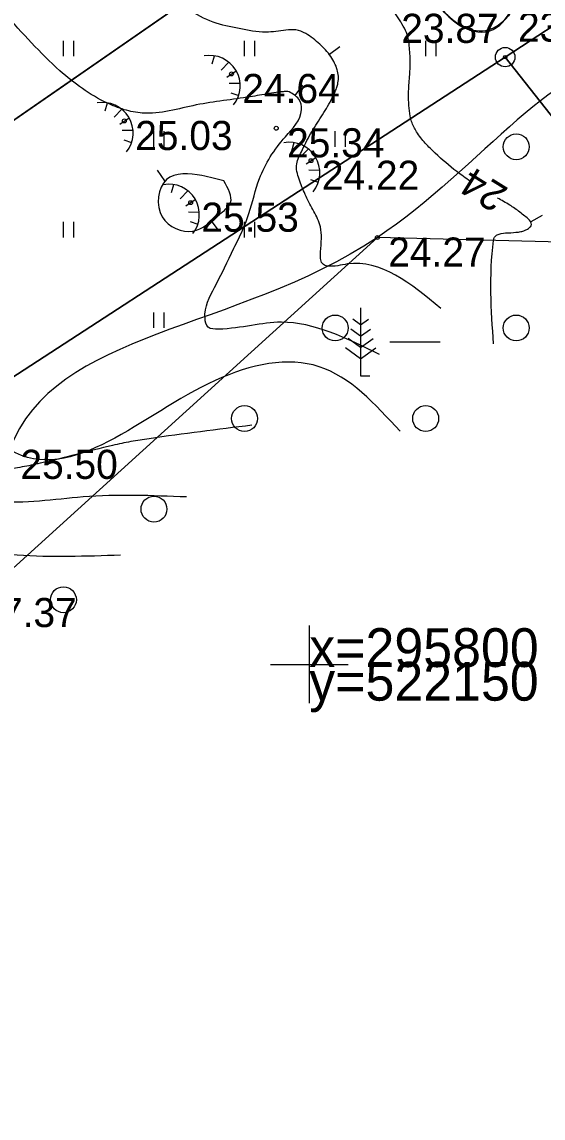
# Model space of a CAD drawing. Extents: x 521824 to 524158, y 294774 to 296228.
# Drawn here: x 522138.9 to 522159.04, y 295782.47 to 295824.83 of the extents above; entities that cross this region are included whole.
import ezdxf

# ---------------------------------------------------------------- set-up
doc = ezdxf.new("R2010")
doc.units = 0
for name, color, linetype in [('GEOD_ELEM_####_####_#', 7, 'Continuous'), ('GEOD_KORD_####_TKST_#', 7, 'Continuous'), ('GL Aizsargjoslas', 7, 'Continuous'), ('GL Atradnes kontura', 7, 'Continuous'), ('GL4 Segkartas izplatības laukums', 7, 'Continuous'), ('RAMI_UZMR_####_####_#', 7, 'Continuous'), ('RELJ_AATZ_####_TKST_#', 7, 'Continuous'), ('RELJ_ELEM_####_####_#', 7, 'Continuous'), ('RELJ_HORZ_####_TKST_#', 7, 'Continuous'), ('RELJ_HORZ_PAMT_####_#', 7, 'Continuous'), ('RELJ_HORZ_RESN_####_#', 7, 'Continuous'), ('RELJ_NOGL_####_####_#', 7, 'Continuous'), ('ROBZ_IERR_####_####_#', 7, 'Continuous'), ('ROBZ_PROJ_####_####_#', 7, 'Continuous'), ('ROBZ_ROBP_####_####_#', 7, 'Continuous'), ('ROBZ_UZMR_####_####_#', 7, 'Continuous'), ('TERT_ELEM_####_####_#', 7, 'Continuous'), ('TERT_KONT_####_####_#', 7, 'Continuous')]:
    doc.layers.add(name, color=color, linetype=linetype)

msp = doc.modelspace()

# ---------------------------------------------------------------- linework, layer by layer
at = {"layer": 'GEOD_ELEM_####_####_#'}
for p, q in [((522150, 295801.5), (522150, 295800)), ((522148.5, 295800), (522150, 295800)), ((522150, 295800), (522150, 295798.5)), ((522150, 295800), (522151.5, 295800))]:
    msp.add_line(p, q, dxfattribs=at)
at = {"layer": 'GL Aizsargjoslas'}
msp.add_lwpolyline([(522131.42829998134, 295816.08118555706), (522115.4941642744, 295836.89638272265), (522093.2463759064, 295865.95927699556), (522070.6576329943, 295896.65064863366), (522048.0688900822, 295927.34202027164), (522034.2954443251, 295950.9093556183), (522016.4452583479, 295981.4522804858), (522014.1669435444, 295985.3506375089), (522007.1170540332, 295997.9066058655), (522041.3600169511, 296024.30747637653), (522061.8608109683, 296026.336216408), (522066.44900074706, 296014.80384880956), (522085.297555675, 295982.5526443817), (522098.68966425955, 295959.6378037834), (522141.23362409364, 295901.9807230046), (522163.3093357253, 295873.1426172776), (522185.385047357, 295844.30451155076), (522186.60753180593, 295842.8705587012), (522172.84800000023, 295833.39200000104), (522161.56349999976, 295826.06900000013), (522160.80220084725, 295825.5718620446), (522154.44700000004, 295832.01500000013)], close=True, dxfattribs=at)
at = {"layer": 'GL Atradnes kontura'}
msp.add_lwpolyline([(521873.29981230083, 295920.72870453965), (521993.22438563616, 295987.195542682), (522041.3600169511, 296024.30747637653), (522231.7470000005, 296043.14800000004), (522231.7470000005, 296043.14800000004), (522324.23810260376, 295937.6804303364), (522172.84800000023, 295833.3920000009), (522160.80220084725, 295825.5718620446), (522154.44700000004, 295832.015), (522095.923, 295791.504), (521999.655, 295722.6060000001), (521986.667353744, 295713.7919047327), (521905.108, 295850.08900000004)], close=True, dxfattribs=at)
at = {"layer": 'GL4 Segkartas izplatības laukums'}
for points in [[(521986.667353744, 295713.7919047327), (521999.655, 295722.6060000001), (522095.923, 295791.504), (522154.44700000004, 295832.015), (522155.467, 295832.737), (522151.58, 295837.93200000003), (522131.531, 295829.31200000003)], [(521986.667353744, 295713.7919047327), (521999.655, 295722.6060000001), (522095.923, 295791.504), (522154.44700000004, 295832.015)]]:
    msp.add_lwpolyline(points, dxfattribs=at)
at = {"layer": 'RAMI_UZMR_####_####_#'}
msp.add_lwpolyline([(522273.7068157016, 295894.679093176), (522210.195, 295852.81900000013), (522168.5796386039, 295826.5640417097), (522172.092, 295817.657), (522169.38300000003, 295816.077), (522152.635, 295816.495), (522136.9981151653, 295802.3114858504), (522118.99319550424, 295793.01918149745), (522105.5356629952, 295782.7157988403), (522092.69590248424, 295770.9148975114), (522080.0709085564, 295765.45019080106), (522059.7754664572, 295749.5723974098), (522015.068, 295726.29200000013), (521978.76, 295706.273), (521927.26800000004, 295670.316), (521927.26800000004, 295670.316)], dxfattribs=at)
at = {"layer": 'RELJ_ELEM_####_####_#'}
for centre in [(522146.99500000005, 295822.816), (522142.856, 295821), (522148.726, 295820.717), (522150.069, 295819.463), (522145.416, 295817.843), (522152.635, 295816.495)]:
    msp.add_circle(centre, 0.075, dxfattribs=at)
at = {"layer": 'RELJ_HORZ_PAMT_####_#'}
for p, q in [((522151.18147001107, 295823.8624858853), (522150.77995715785, 295823.5645136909)), ((522149.74117743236, 295822.3873823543), (522149.4474779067, 295821.98273363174)), ((522144.11930693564, 295819.0974037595), (522144.4015569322, 295818.68468722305)), ((522146.5165093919, 295816.74320777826), (522146.2200621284, 295817.14584784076))]:
    msp.add_line(p, q, dxfattribs=at)
for points in [[(522155.0886326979, 295813.7557682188), (522151.476, 295815.473), (522150.71826181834, 295815.389049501), (522150.5862896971, 295815.42597728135), (522150.52854061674, 295815.47447047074), (522150.47868407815, 295815.5347646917), (522150.44324609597, 295815.6375122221), (522150.43173358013, 295815.74036507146), (522150.4391822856, 295815.9464990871), (522150.46838180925, 295816.45870181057), (522150.4349080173, 295816.90582198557), (522150.32474293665, 295817.2145605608), (522150.1765778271, 295817.5027550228), (522150.01787933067, 295817.7872859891), (522149.87611409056, 295818.08503407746), (522149.6311337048, 295818.676462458), (522149.5413839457, 295818.97274512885), (522149.5087661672, 295819.2679475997), (522149.5717148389, 295819.5406712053), (522149.6961199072, 295819.8111694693), (522150.04808579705, 295820.49597701), (522150.4633809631, 295821.15874725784), (522150.8487202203, 295821.81196673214), (522151.0054159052, 295822.13498454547), (522151.0653793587, 295822.3016255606), (522151.1108183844, 295822.46812195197), (522151.08124367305, 295822.9800416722), (522150.9790835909, 295823.2377439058), (522150.83558654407, 295823.4863580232), (522150.63192145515, 295823.743199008), (522150.40351131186, 295823.9623009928), (522149.86767140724, 295824.37511899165), (522149.483322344, 295824.515168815), (522149.09662563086, 295824.50202654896), (522148.3275090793, 295824.43049952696), (522147.29810929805, 295824.5667778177), (522146.28248527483, 295824.8153967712), (522145.34491229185, 295825.30232815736), (522144.5093302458, 295825.94019956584), (522143.6871954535, 295826.6164684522), (522142.78996423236, 295827.2185922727), (522141.14813151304, 295828.13647943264), (522139.49188041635, 295828.99756603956), (522138.2636715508, 295829.48696327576), (522137.62725926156, 295829.6749554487), (522136.9780723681, 295829.84254225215), (522136.1317401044, 295829.92734415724), (522135.6191257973, 295829.89386764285), (522135.10742949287, 295829.8271999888), (522134.0950111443, 295829.5634693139), (522133.5829063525, 295829.36426225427), (522133.0776602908, 295829.154088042), (522132.08546766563, 295828.6959858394), (522132.08546766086, 295828.6959858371)], [(522152.7209302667, 295811.9707504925), (522148.922, 295813.223), (522146.4960566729, 295812.95285345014), (522146.08901685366, 295813.0354322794), (522145.9720596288, 295813.3717736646), (522146.34466346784, 295814.5702659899), (522147.08640919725, 295816.07737419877), (522147.4308793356, 295816.7994854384), (522147.66983782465, 295817.4221420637), (522148.0783060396, 295818.769915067), (522149.07821115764, 295820.38812970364), (522149.701382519, 295821.43320285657), (522149.5973275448, 295821.84146745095), (522149.39522283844, 295822.01905765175), (522149.16865251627, 295822.13533768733), (522148.98804895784, 295822.12820417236), (522148.807367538, 295822.1116989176), (522148.44590315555, 295822.05891415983), (522147.72349250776, 295821.93263444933), (522145.6362983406, 295821.6156163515), (522143.5491777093, 295821.3041340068), (522142.8513816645, 295821.43490923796), (522142.181413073, 295821.6948699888), (522140.36686331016, 295822.94053305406), (522138.22832208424, 295825.1645472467), (522136.13580558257, 295827.2091944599), (522135.0130714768, 295827.88370627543), (522134.10680587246, 295828.14536728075), (522133.78936140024, 295828.17671733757), (522132.9252140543, 295828.06282948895), (522132.070146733, 295827.7197229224), (522132.0682195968, 295827.71872579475)], [(522153.5118563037, 295809.01013146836), (522150.38469259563, 295811.5042940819), (522146.368, 295810.972), (522138.4187270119, 295808.2884077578), (522138.4111714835, 295808.2929389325), (522138.35737339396, 295808.39614236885), (522137.6989059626, 295810.12618072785), (522137.18428464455, 295811.8847708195), (522136.3260308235, 295815.45203936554), (522135.26151288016, 295819.02681433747), (522134.4890614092, 295820.79478746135), (522134.01428994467, 295821.6700303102), (522133.4696317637, 295822.53796206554), (522132.8264651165, 295823.41468231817), (522132.0777502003, 295824.1945613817), (522131.2615746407, 295824.6733362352), (522130.79921845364, 295824.7332702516)], [(522145.261, 295806.471), (522141.261, 295806.471), (522137.86903952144, 295806.3054456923), (522137.15343648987, 295806.47794995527), (522136.5369331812, 295806.96730999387), (522135.98349919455, 295807.6175017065), (522135.45710412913, 295808.2725009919), (522135.0446612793, 295808.77773966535), (522133.9899686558, 295810.37233287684), (522132.8153101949, 295812.604144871), (522131.59961082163, 295814.8336071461), (522130.8721464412, 295815.9054790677), (522130.0093526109, 295816.926389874), (522128.4706857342, 295818.2778510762), (522127.6222263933, 295818.740803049), (522126.9919833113, 295818.9340508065)], [(522146.69649181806, 295818.68832586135), (522146.9571093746, 295817.843), (522146.5156293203, 295817.3769267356), (522145.5002251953, 295816.7437825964), (522144.32294505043, 295817.2885810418), (522144.4848210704, 295818.7315607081), (522145.85017811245, 295818.88615340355), (522146.69649181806, 295818.68832586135)], [(522142.70700000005, 295804.22000000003), (522138.70700000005, 295804.22000000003), (522137.34479515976, 295804.4142679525), (522136.2316160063, 295804.9242351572), (522135.3688927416, 295805.9120758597), (522134.62824842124, 295807.1128452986), (522134.26358807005, 295807.71028305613), (522133.8813061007, 295808.2615987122), (522132.9948357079, 295809.50285371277), (522132.1619797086, 295810.7682383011), (522131.3148710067, 295812.0332292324), (522130.38564250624, 295813.2733032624), (522128.14382295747, 295815.4873034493), (522126.85108977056, 295816.3337912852), (522126.165541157, 295816.6677094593), (522125.8105958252, 295816.8138745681)]]:
    msp.add_spline(points, degree=3, dxfattribs=at)
at = {"layer": 'RELJ_HORZ_RESN_####_#'}
msp.add_line((522158.99729686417, 295817.34749814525), (522158.5611925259, 295817.1029311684), dxfattribs=at)
for points in [[(522156.22495517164, 295818.6665641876), (522155.6981013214, 295819.0453375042), (522154.8730313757, 295819.7508152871), (522154.4856175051, 295820.13993791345), (522154.3098000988, 295820.3524200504), (522154.1458149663, 295820.58429111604), (522153.957065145, 295820.97362192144), (522153.87014079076, 295821.38820887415), (522153.8460009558, 295822.2367798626), (522153.85700568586, 295822.4525511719), (522153.87377385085, 295822.6683109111), (522153.89038104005, 295822.8840702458), (522153.90090284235, 295823.09984034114), (522153.8951767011, 295823.523522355), (522153.8807982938, 295823.7353788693), (522153.8623538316, 295823.9472265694), (522153.75897860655, 295824.41261030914), (522153.58259215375, 295824.7465385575), (522153.38456283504, 295825.06209191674), (522152.947978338, 295825.6579813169), (522152.4980305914, 295826.24009320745), (522152.083525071, 295826.8482422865), (522151.751736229, 295827.4026416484), (522151.6042741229, 295827.6923860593), (522151.4676253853, 295827.9973066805), (522151.3411701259, 295828.33443643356), (522151.29008462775, 295828.50718338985), (522151.2477544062, 295828.6840761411), (522151.20528462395, 295829.38167341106), (522151.26103220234, 295829.9282333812)], [(522157.12600000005, 295812.38300000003), (522157.12600000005, 295816.38300000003), (522157.1625074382, 295816.51434187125), (522157.26199968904, 295816.5978323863), (522157.5897582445, 295816.6698276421), (522157.98891490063, 295816.69612235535), (522158.1776547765, 295816.7224871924), (522158.3391088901, 295816.77385311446), (522158.4713650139, 295816.8417822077), (522158.5289237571, 295816.8889941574), (522158.57737787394, 295816.9412963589), (522158.5107709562, 295817.1679255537), (522158.32675243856, 295817.3262576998), (522158.1401947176, 295817.4762158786), (522157.94820340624, 295817.6167817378), (522157.74788411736, 295817.7469369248), (522157.27520165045, 295818.0198425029)], [(522147.78104149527, 295809.2411104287), (522143.815, 295808.721), (522143.1063807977, 295808.60745946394), (522142.40154824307, 295808.4608412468), (522140.9999922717, 295808.1138383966), (522139.60383047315, 295807.77092470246), (522138.90574063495, 295807.6294179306), (522138.5563379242, 295807.57112497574), (522138.20656123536, 295807.52303341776), (522137.8660891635, 295807.5612298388), (522137.70095343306, 295807.63237646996), (522137.5449367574, 295807.7315936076), (522137.3874805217, 295807.8629645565), (522137.24505425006, 295807.99999662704), (522136.9578823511, 295808.2828842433), (522136.29702987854, 295808.97770171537), (522135.85689479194, 295809.5103869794), (522135.4615186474, 295810.07660131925), (522135.11437151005, 295810.6728496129), (522134.8189234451, 295811.29563673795), (522134.3848895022, 295812.37532344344), (522133.971706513, 295813.46102050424)]]:
    msp.add_spline(points, degree=3, dxfattribs=at)
at = {"layer": 'RELJ_NOGL_####_####_#'}
msp.add_spline([(522157.77300000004, 295827.023), (522157.87200000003, 295825.368), (522156.8138430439, 295824.483601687), (522155.071, 295825.376), (522154.4157255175, 295826.43018908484), (522151.8136290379, 295829.3257378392), (522140.98600000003, 295841.081), (522130.14800000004, 295854.6060000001), (522118.868, 295867.895), (522112.737, 295876.058), (522113.2986392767, 295878.0255479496), (522113.824, 295878.38800000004), (522115.39200000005, 295878.049)], degree=3, dxfattribs=at)
at = {"layer": 'ROBZ_IERR_####_####_#'}
msp.add_lwpolyline([(521982.72142177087, 296071.9435568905), (522030.7829999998, 296022.79399999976), (522033.55399999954, 296023.53500000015), (522231.7470000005, 296043.14800000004), (522293.95000000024, 296059.25), (522300.4160000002, 296060.9240000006), (522337.1440000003, 296010.44299999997), (522362.11199999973, 295976.4340000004), (522359.108, 295971.28500000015), (522349.7560000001, 295955.2589999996), (522172.84800000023, 295833.3920000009), (522168.0970000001, 295830.30399999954), (522159.466, 295824.6950000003), (522157.57199999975, 295823.4639999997), (522100.0300000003, 295786.06900000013), (522037.6330000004, 295748.40699999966), (521945.6600000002, 295684.5130000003), (521914.93752583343, 295661.4435568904)], dxfattribs=at)
at = {"layer": 'ROBZ_PROJ_####_####_#'}
msp.add_lwpolyline([(522213.36799999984, 295752.79099999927), (522157.57199999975, 295823.4639999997), (522159.466, 295824.6950000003), (522168.0970000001, 295830.30399999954), (522223.0959999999, 295760.6429999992)], dxfattribs=at)
at = {"layer": 'ROBZ_ROBP_####_####_#'}
for radius in [0.375, 0.07022819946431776]:
    msp.add_circle((522157.57199999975, 295823.4639999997), radius, dxfattribs=at)
at = {"layer": 'ROBZ_UZMR_####_####_#'}
msp.add_lwpolyline([(521956.07739950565, 295661.4435568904), (521945.6600000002, 295684.5130000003), (522037.6330000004, 295748.40699999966), (522100.0300000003, 295786.06900000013), (522157.57199999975, 295823.4639999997), (522213.36799999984, 295752.79099999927)], dxfattribs=at)
at = {"layer": 'TERT_ELEM_####_####_#'}
for p, q in [((522140.5, 295823.5), (522140.5, 295824.10000000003)), ((522140.9, 295823.5), (522140.9, 295824.10000000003)), ((522147.5, 295823.5), (522147.5, 295824.10000000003)), ((522147.9, 295823.5), (522147.9, 295824.10000000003)), ((522154.5, 295823.5), (522154.5, 295824.10000000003)), ((522154.9, 295823.5), (522154.9, 295824.10000000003)), ((522146.2525, 295823.20225000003), (522146.34400000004, 295823.51425)), ((522146.5945, 295822.96375), (522146.89300000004, 295823.27125)), ((522146.81350000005, 295822.69225), (522147.1765, 295822.93975)), ((522146.911, 295822.46275), (522147.32950000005, 295822.45375)), ((522146.97250000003, 295822.08475000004), (522147.277, 295821.98875)), ((522142.11350000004, 295821.38625000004), (522142.205, 295821.69825)), ((522142.45550000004, 295821.14775), (522142.754, 295821.45525)), ((522142.6745, 295820.87625000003), (522143.03750000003, 295821.12375)), ((522142.772, 295820.64675), (522143.1905, 295820.63775)), ((522144, 295820), (522144, 295820.60000000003)), ((522144.4, 295820), (522144.4, 295820.60000000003)), ((522151, 295820), (522151, 295820.60000000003)), ((522151.4, 295820), (522151.4, 295820.60000000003)), ((522142.8335, 295820.26875), (522143.13800000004, 295820.17275)), ((522149.3265, 295819.84925), (522149.418, 295820.16125)), ((522149.6685, 295819.61075), (522149.967, 295819.91825)), ((522149.8875, 295819.33925), (522150.2505, 295819.58675)), ((522149.98500000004, 295819.10975), (522150.4035, 295819.10075000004)), ((522150.0465, 295818.73175000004), (522150.351, 295818.63575)), ((522144.67350000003, 295818.22925000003), (522144.765, 295818.54125)), ((522145.01550000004, 295817.99075), (522145.314, 295818.29825)), ((522145.2345, 295817.71925), (522145.59750000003, 295817.96675)), ((522145.33200000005, 295817.48975), (522145.7505, 295817.48075)), ((522140.5, 295816.5), (522140.5, 295817.10000000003)), ((522140.9, 295816.5), (522140.9, 295817.10000000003)), ((522145.3935, 295817.11175000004), (522145.69800000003, 295817.01575)), ((522147.5, 295816.5), (522147.5, 295817.10000000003)), ((522147.9, 295816.5), (522147.9, 295817.10000000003)), ((522144, 295813), (522144, 295813.60000000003)), ((522144.4, 295813), (522144.4, 295813.60000000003)), ((522151.9853433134, 295813.77566694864), (522151.9853433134, 295811.15066694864)), ((522151.9853433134, 295813.1171669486), (522151.67934331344, 295813.34066694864)), ((522151.9853433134, 295813.1171669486), (522152.2928433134, 295813.34066694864)), ((522151.9853433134, 295812.6806669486), (522151.6088433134, 295812.9551669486)), ((522151.9853433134, 295812.6806669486), (522152.3648433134, 295812.9551669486)), ((522151.9853433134, 295812.24266694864), (522151.49934331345, 295812.5996669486)), ((522151.9853433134, 295812.24266694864), (522152.4743433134, 295812.5996669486)), ((522153.1103433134, 295812.46316694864), (522155.06034331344, 295812.46316694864)), ((522151.9853433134, 295811.8046669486), (522151.40634331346, 295812.2321669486)), ((522151.9853433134, 295811.8046669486), (522152.57184331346, 295812.2321669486)), ((522151.9853433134, 295811.15066694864), (522152.33634331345, 295811.15066694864))]:
    msp.add_line(p, q, dxfattribs=at)
for centre in [(522158, 295820), (522151, 295813), (522158, 295813), (522147.5, 295809.5), (522154.5, 295809.5), (522144, 295806), (522140.5, 295802.5)]:
    msp.add_circle(centre, 0.5, dxfattribs=at)
for centre in [(522146.158037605, 295822.35251024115), (522142.01903760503, 295820.53651024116), (522149.232037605, 295818.99951024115), (522144.579037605, 295817.37951024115)]:
    msp.add_arc(centre, 1.1762394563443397, 321.44048343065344, 100.46343407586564, dxfattribs=at)
at = {"layer": 'TERT_KONT_####_####_#'}
for points in [[(522112.737, 295876.058), (522112.737, 295877.51455323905), (522113.8446896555, 295878.3905175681), (522123.086, 295867.722), (522132.03, 295856.813), (522140.951, 295846.381), (522148.93700000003, 295836.168), (522157.87200000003, 295825.368), (522156.95989990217, 295824.47003253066), (522155.7794142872, 295824.7184870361), (522155.071, 295825.376), (522140.98600000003, 295841.081), (522129.85114007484, 295854.43447290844), (522118.868, 295867.895), (522112.737, 295876.058)], [(522167.4830389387, 295816.12441961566), (522162.42248847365, 295823.1181618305), (522152.635, 295816.495), (522138.42000000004, 295808.293), (522136.83300000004, 295802.5680000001), (522123.45, 295801.50700000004), (522122.24000000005, 295804.162), (522130.90400000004, 295808.24100000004), (522129.362, 295823.211)]]:
    msp.add_spline(points, degree=3, dxfattribs=at)

# ---------------------------------------------------------------- texts
at = {"layer": 'GEOD_KORD_####_TKST_#'}
for s, p in [('x=295800', (522150, 295799.9)), ('y=522150', (522150, 295798.60000000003))]:
    msp.add_text(s, height=1.5, dxfattribs=at).set_placement(p)
at = {"layer": 'RELJ_AATZ_####_TKST_#'}
for s, p in [(' 23.87', (522153.1394036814, 295824.01462867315)), (' 23.67', (522157.6496579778, 295824.0622454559)), (' 24.64', (522146.99500000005, 295821.691)), (' 25.03', (522142.856, 295819.875)), (' 25.34', (522148.726, 295819.592)), (' 24.22', (522150.069, 295818.338)), (' 25.53', (522145.416, 295816.718)), (' 24.27', (522152.635, 295815.37)), (' 25.50', (522138.42000000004, 295807.168)), (' 27.37', (522136.83300000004, 295801.4430000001))]:
    msp.add_text(s, height=1.125, dxfattribs=at).set_placement(p)
at = {"layer": 'RELJ_HORZ_####_TKST_#'}
msp.add_text('24', height=1.1249999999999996, rotation=148.1570170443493, dxfattribs=at).set_placement((522157.74000913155, 295818.37330709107))

doc.saveas('drawing.dxf')
